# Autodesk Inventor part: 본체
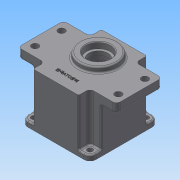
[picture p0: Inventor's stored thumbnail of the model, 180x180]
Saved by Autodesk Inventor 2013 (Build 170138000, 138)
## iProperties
Created: 2014-12
Part Number: 본체
Material: Generic
Document SubType Name: Modeling
Designer: Administrator
Density: 1 g/cm^3
Author: Administrator
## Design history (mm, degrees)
sketch "Sketch1"
  geometry: L1 (-37, 45)-(37, 45); L2 (45, 37)-(45, -37); L3 (37, -45)-(-37, -45); L4 (-45, -37)-(-45, 37); L5 (-45, 45)-(45, -45); L6 (45, 45)-(-45, -45); C1 r 3.5 at (-37, 37); C2 r 3.5 at (37, 37); C3 r 3.5 at (37, -37); C4 r 3.5 at (-37, -37); A1 r 8 centre (-37, 37) between (-37, 45) and (-45, 37); A2 r 8 centre (37, 37) between (45, 37) and (37, 45); A3 r 8 centre (37, -37) between (37, -45) and (45, -37); A4 r 8 centre (-37, -37) between (-45, -37) and (-37, -45); 1 further point
  constraints: 12 end point, 8 centre point, 8 point on circle, 8 point on line, 8 tangent, 4 coincident, 3 equal radius, 2 midpoint, 2 parallel, 1 horizontal, 1 perpendicular
  dimensions: "d0" = 90 distance of L5.end L6.end; "d1" = 90 distance of L6.start L5.end; "d2" = 8 radius of A1; "d3" = 7 diameter of C1; "d4" = 7 diameter of C2; "d5" = 7 diameter of C3; "d6" = 7 diameter of C4
extrude "Extrusion1" new body sketch "Sketch1" distance "d7" = 7; taper "d8" = 0 deg
sketch "Sketch2"
  geometry: L1 (-30, 45)-(30, 45); L2 (30, 45)-(30, -45); L3 (30, -45)-(-30, -45); L4 (-30, -45)-(-30, 45); L5 (-30, 45)-(30, -45); L6 (30, 45)-(-30, -45); L7 (-45, 30)-(45, 30); L8 (45, 30)-(45, -30); L9 (45, -30)-(-45, -30); L10 (-45, -30)-(-45, 30); L11 (-45, 30)-(45, -30); L12 (45, 30)-(-45, -30); 1 further point
  constraints: 24 end point, 4 midpoint, 4 parallel, 2 horizontal, 2 perpendicular
  dimensions: "d9" = 60 distance of L2.end L3.end; "d10" = 90 distance of L1.end L2.end; "d11" = 90 distance of L8.end L9.end; "d12" = 60 distance of L7.end L8.end
extrude "Extrusion2" join sketch "Sketch2" distance "d13" = 51; taper "d14" = 0 deg
sketch "Sketch3"
  geometry: L1 (-30, -30)-(-30, -45) reference; L2 (-30, -45)-(30, -45) reference; L3 (30, -45)-(30, -30) reference; L4 (30, -30)-(45, -30) reference; L5 (45, -30)-(45, 30) reference; L6 (45, 30)-(30, 30) reference; L7 (30, 30)-(30, 45) reference; L8 (30, 45)-(-30, 45) reference; L9 (-30, 45)-(-30, 30) reference; L10 (-30, 30)-(-45, 30) reference; L11 (-45, 30)-(-45, -30) reference; L12 (-45, -30)-(-30, -30) reference; L13 (-60, 30)-(60, 30); L14 (65, 25)-(65, -25); L15 (60, -30)-(-60, -30); L16 (-65, -25)-(-65, 25); L17 (-65, 30)-(65, -30); L18 (65, 30)-(-65, -30); A1 r 5 centre (-60, 25) between (-60, 30) and (-65, 25); A2 r 5 centre (60, 25) between (65, 25) and (60, 30); A3 r 5 centre (60, -25) between (60, -30) and (65, -25); A4 r 5 centre (-60, -25) between (-65, -25) and (-60, -30); 5 further points
  constraints: 12 end point, 8 point on circle, 8 point on line, 8 tangent, 4 centre point, 3 equal radius, 2 horizontal alignment, 2 midpoint, 2 parallel, 2 vertical alignment, 1 horizontal, 1 perpendicular
  dimensions: "d15" = 130 distance of L17.end L18.end; "d16" = 60 distance of L18.start L17.end; "d19" = 5 radius of A1; "d20" = 10 distance from line of L16 point (-55, 17.5); "d21" = 12.5 distance from line of L13 point (-55, 17.5); "d22" = 110 distance of point (55, 17.5) point (-55, 17.5); "d23" = 35 distance of point (-55, 17.5) point (-55, -17.5)
extrude "Extrusion3" join sketch "Sketch3" distance "d17" = 12; taper "d18" = 0 deg
hole "Hole1" sketch "Sketch3" diameter "d24" = 9; stored, may be unused: countersink angle "d28" = 90 deg, drill point angle "d30" = 118 deg; dims "d25" = 6, "d26" = 4, "d27" = 2, "d29" = 8
sketch "Sketch4"
  geometry: C1 r 25 at (0, 11); 1 further point
  constraints: 1 centre point, 1 vertical alignment
  dimensions: "d31" = 50 diameter of C1; "d32" = 11 distance of point (0, 0) C1.centre
extrude "Extrusion4" join sketch "Sketch4" distance "d33" = 7; taper "d34" = 0 deg
sketch "Sketch5"
  geometry: C1 r 40 at (0, 0); 1 further point
  constraints: 1 centre point, 1 coincident
  dimensions: "d35" = 80 diameter of C1
extrude "Extrusion5" cut sketch "Sketch5" distance "d36" = 9; taper "d37" = 0 deg
sketch "Sketch6"
  geometry: C1 r 40 at (0, 0) reference; C2 r 39 at (0, 0)
  constraints: 1 centre point, 1 coincident
  dimensions: "d38" = 78 diameter of C2
extrude "Extrusion6" cut sketch "Sketch6" distance "d39" = 52; taper "d40" = 0 deg
sketch "Sketch7"
  geometry: L1 (0, 0)-(0, 39); C1 r 40 at (0, 0) reference; A1 r 39 centre (0, 0) between (0, 39) and (32.777, 21.134) reference; A2 r 4 centre (24.749, 24.749) between (21.809, 27.462) and (27.462, 21.809); A3 r 3.5 centre (19.238, 29.836) between (21.809, 27.462) and (21.134, 32.777); A4 r 3.5 centre (29.836, 19.238) between (32.777, 21.134) and (27.462, 21.809); 1 further point
  constraints: 9 point on circle, 4 tangent, 3 centre point, 2 end point, 1 coincident, 1 vertical
  dimensions: "d41" = 8 diameter of A2; "d42" = 35 distance of A1.centre A2.centre; "d43" = 45 deg dimension on A1.centre A2.centre L1.end; "d44" = 7 diameter of A3; "d45" = 7 diameter of A4
extrude "Extrusion7" join sketch "Sketch7" stored distance "d46" = 52; taper "d47" = 0 deg
hole "Hole2" sketch "Sketch7" diameter "d48" = 3.459; stored, may be unused: countersink angle "d52" = 90 deg, drill point angle "d54" = 118 deg; dims "d49" = 12, "d50" = 4, "d51" = 2, "d53" = 15
pattern_circular "Circular Pattern1" dims angle "d56" = 360 deg
sketch "Sketch8"
  geometry: A1 r 39 centre (0, 0) between (-32.777, 21.134) and (-32.777, -21.134) reference; A2 r 20.5 centre (0, 11) between (11.115, -6.225) and (-11.115, -6.225); A3 r 14 centre (0, -20) between (-10.493, -10.732) and (10.493, -10.732); A4 r 3 centre (-12.742, -8.746) between (-10.493, -10.732) and (-11.115, -6.225); A5 r 3 centre (12.742, -8.746) between (11.115, -6.225) and (10.493, -10.732)
  constraints: 8 point on circle, 4 centre point, 4 tangent, 2 vertical alignment, 1 equal radius
  dimensions: "d58" = 41 diameter of A2; "d59" = 28 diameter of A3; "d60" = 11 distance of A1.centre A2.centre; "d61" = 20 distance of A3.centre A1.centre; "d62" = 3 radius of A4
extrude "Extrusion8" join sketch "Sketch8" distance "d63" = 7; taper "d64" = 0 deg
sketch "Sketch9"
  geometry: C1 r 25 at (0, 0) reference; 2 further points
  constraints: 1 coincident
hole "Hole3" sketch "Sketch9" at (0, 0) diameter "d65" = 25; stored, may be unused: countersink angle "d69" = 90 deg, drill point angle "d71" = 118 deg; dims "d66" = 12, "d67" = 32, "d68" = 8, "d70" = 15
sketch "Sketch10"
  geometry: C1 r 12.5 at (0, 11) reference; C2 r 17.5 at (0, 11); A1 r 14 centre (0, -20) between (-10.493, -10.732) and (10.493, -10.732) reference; A2 r 20.5 centre (0, 11) between (11.115, -6.225) and (-11.115, -6.225) reference; 2 further points
  constraints: 2 coincident, 1 centre point
  dimensions: "d72" = 35 diameter of C2
extrude "Extrusion9" cut sketch "Sketch10" distance "d73" = 10; taper "d74" = 0 deg
hole "Hole4" sketch "Sketch10" diameter "d75" = 19; stored, may be unused: countersink angle "d79" = 90 deg, drill point angle "d81" = 0 deg; dims "d76" = 12, "d77" = 22, "d78" = 7, "d80" = 8
chamfer "Chamfer1" distance "d82" = 1; stored, may be unused: second distance "d83" = 2, angle "d84" = 45 deg
fillet "Fillet1" dims "d85" = 5, "d86" = 0.3, "d87" = 2
sketch "Sketch11"
  geometry: L1 (-28, -45)-(28, -45) reference; C1 r 27 at (0, 11) reference; 2 further points
  constraints: 1 vertical alignment, 1 other
  dimensions: "d88" = 15 distance from line of L1 point (0, -30)
emboss "Emboss1" sketch "Sketch11" dims "d0" = 90, "d1" = 90, "d2" = 8, "d3" = 7, "d4" = 7, "d5" = 7, "d6" = 7, "d89" = 0.5, "d90" = 0
body "Solid1"
